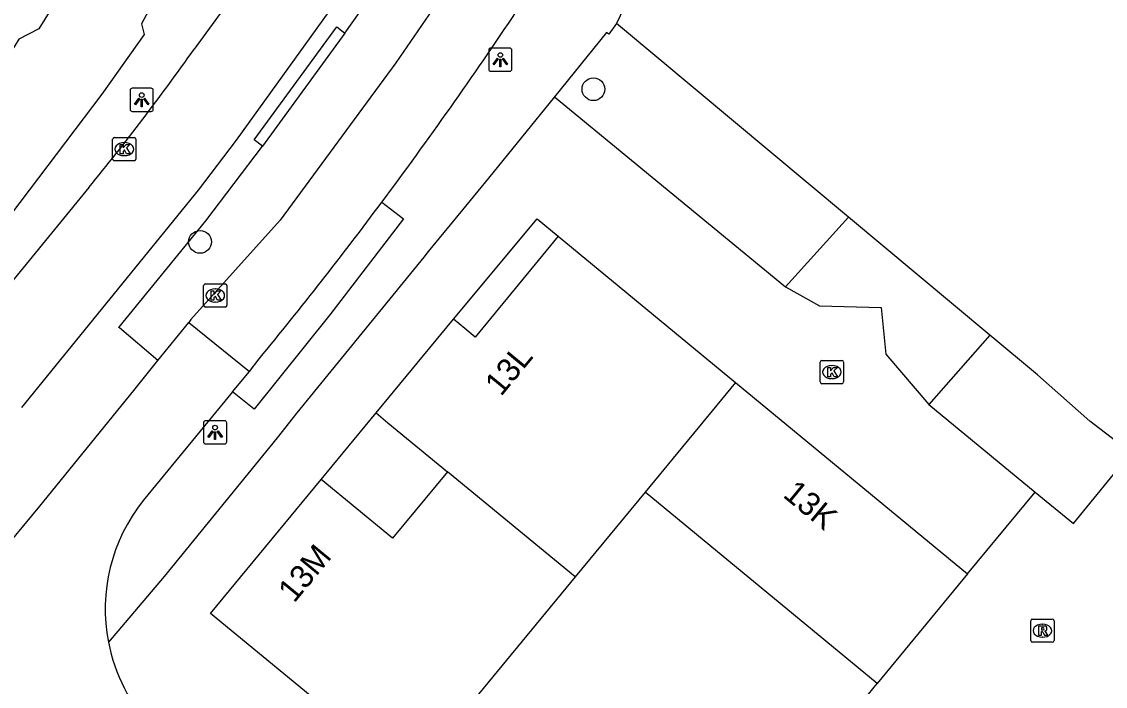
# Model space of a CAD drawing. Extents: x 161772 to 163123, y 383092 to 383917.
# Drawn here: x 161951.08 to 161997.61, y 383296.33 to 383324.88 of the extents above; entities that cross this region are included whole.
import ezdxf

# ---------------------------------------------------------------- set-up
doc = ezdxf.new("R2010")
doc.units = 0
for name, color, linetype in [('IMGEO_Berm_open', 7, 'Continuous'), ('IMGEO_Boom', 7, 'Continuous'), ('IMGEO_Fietspad_gesloten', 7, 'Continuous'), ('IMGEO_Groenvoorziening', 7, 'Continuous'), ('IMGEO_Kolk', 7, 'Continuous'), ('IMGEO_Lichtpunt', 7, 'Continuous'), ('IMGEO_Pand', 7, 'Continuous'), ('IMGEO_Pand_nummerreeks', 7, 'Continuous'), ('IMGEO_Parkeervlak_open', 7, 'Continuous'), ('IMGEO_Rijbaan_lokaal_gesloten', 7, 'Continuous'), ('IMGEO_Rijbaan_lokaal_open', 7, 'Continuous'), ('IMGEO_Rioolput', 7, 'Continuous'), ('IMGEO_Voetpad_open', 7, 'Continuous')]:
    doc.layers.add(name, color=color, linetype=linetype)

msp = doc.modelspace()

# ---------------------------------------------------------------- linework, layer by layer
at = {"layer": 'IMGEO_Berm_open'}
msp.add_lwpolyline([(161961.426, 383319.531), (161961.064, 383319.803), (161964.615, 383324.66), (161964.958, 383324.39)], dxfattribs=at)
at = {"layer": 'IMGEO_Boom'}
for centre in [(161975.629, 383321.983), (161958.739, 383315.426)]:
    msp.add_circle(centre, 0.489, dxfattribs=at)
at = {"layer": 'IMGEO_Fietspad_gesloten'}
for points in [[(161961.539, 383327.899), (161958.488, 383323.707)], [(161951.08, 383308.304), (161958.672, 383317.649), (161960.302, 383319.794), (161965.764, 383327.377)], [(161953.961, 383317.758), (161942.798, 383304.121), (161935.389, 383295.477), (161886.612, 383242.159)]]:
    msp.add_lwpolyline(points, dxfattribs=at)
msp.add_arc((161873.405, 383383.756), 104.139, 320.6731, 324.78693, dxfattribs=at)
at = {"layer": 'IMGEO_Groenvoorziening'}
for points in [[(161983.878, 383313.491), (161986.582, 383316.493)], [(161992.656, 383311.418), (161990.027, 383308.434)]]:
    msp.add_lwpolyline(points, dxfattribs=at)
at = {"layer": 'IMGEO_Kolk'}
for p, q in [((161955.062, 383319.909), (161955.914, 383319.909)), ((161954.987, 383318.983), (161954.987, 383319.835)), ((161955.475, 383319.689), (161955.5, 383319.689)), ((161955.988, 383319.835), (161955.988, 383318.983)), ((161955.498, 383319.129), (161955.473, 383319.129)), ((161955.914, 383318.909), (161955.062, 383318.909)), ((161958.894, 383312.695), (161958.894, 383313.547)), ((161958.969, 383313.621), (161959.821, 383313.621)), ((161959.382, 383313.401), (161959.407, 383313.401)), ((161959.895, 383313.547), (161959.895, 383312.695)), ((161959.821, 383312.621), (161958.969, 383312.621)), ((161959.405, 383312.841), (161959.38, 383312.841)), ((161985.367, 383309.406), (161985.367, 383310.258)), ((161985.442, 383310.332), (161986.294, 383310.332)), ((161985.855, 383310.112), (161985.88, 383310.112)), ((161986.368, 383310.258), (161986.368, 383309.406)), ((161986.294, 383309.332), (161985.442, 383309.332)), ((161985.878, 383309.552), (161985.853, 383309.552))]:
    msp.add_line(p, q, dxfattribs=at)
for points in [[(161955.062, 383319.909), (161955.914, 383319.909)], [(161954.987, 383318.983), (161954.987, 383319.835)], [(161955.308, 383319.609), (161955.431, 383319.609), (161955.431, 383319.458), (161955.561, 383319.609), (161955.725, 383319.609), (161955.579, 383319.458), (161955.732, 383319.209), (161955.58, 383319.209), (161955.495, 383319.373), (161955.431, 383319.306), (161955.431, 383319.209), (161955.308, 383319.209), (161955.308, 383319.609)], [(161955.988, 383319.835), (161955.988, 383318.983)], [(161955.914, 383318.909), (161955.062, 383318.909)], [(161958.894, 383312.695), (161958.894, 383313.547)], [(161958.969, 383313.621), (161959.821, 383313.621)], [(161959.895, 383313.547), (161959.895, 383312.695)], [(161959.215, 383313.321), (161959.338, 383313.321), (161959.338, 383313.17), (161959.468, 383313.321), (161959.632, 383313.321), (161959.486, 383313.17), (161959.639, 383312.921), (161959.487, 383312.921), (161959.402, 383313.085), (161959.338, 383313.018), (161959.338, 383312.921), (161959.215, 383312.921), (161959.215, 383313.321)], [(161959.821, 383312.621), (161958.969, 383312.621)], [(161985.367, 383309.406), (161985.367, 383310.258)], [(161985.442, 383310.332), (161986.294, 383310.332)], [(161986.368, 383310.258), (161986.368, 383309.406)], [(161985.688, 383310.032), (161985.811, 383310.032), (161985.811, 383309.881), (161985.941, 383310.032), (161986.105, 383310.032), (161985.959, 383309.881), (161986.112, 383309.632), (161985.96, 383309.632), (161985.875, 383309.796), (161985.811, 383309.729), (161985.811, 383309.632), (161985.688, 383309.632), (161985.688, 383310.032)], [(161986.294, 383309.332), (161985.442, 383309.332)]]:
    msp.add_lwpolyline(points, dxfattribs=at)
for centre, start, end in [((161955.064, 383319.833), 91.552, 178.448), ((161955.064, 383319.833), 91.552, 178.448), ((161955.912, 383319.833), 1.552, 88.448), ((161955.912, 383319.833), 1.552, 88.448), ((161955.064, 383318.985), 181.552, 268.448), ((161955.064, 383318.985), 181.552, 268.448), ((161955.912, 383318.985), 271.552, 358.448), ((161955.912, 383318.985), 271.552, 358.448), ((161958.971, 383313.545), 91.552, 178.448), ((161958.971, 383313.545), 91.552, 178.448), ((161959.819, 383313.545), 1.552, 88.448), ((161959.819, 383313.545), 1.552, 88.448), ((161958.971, 383312.697), 181.552, 268.448), ((161958.971, 383312.697), 181.552, 268.448), ((161959.819, 383312.697), 271.552, 358.448), ((161959.819, 383312.697), 271.552, 358.448), ((161985.444, 383310.256), 91.552, 178.448), ((161985.444, 383310.256), 91.552, 178.448), ((161986.292, 383310.256), 1.552, 88.448), ((161986.292, 383310.256), 1.552, 88.448), ((161985.444, 383309.408), 181.552, 268.448), ((161985.444, 383309.408), 181.552, 268.448), ((161986.292, 383309.408), 271.552, 358.448), ((161986.292, 383309.408), 271.552, 358.448)]:
    msp.add_arc(centre, 0.0765, start, end, dxfattribs=at)
for centre, major_axis, ratio, start_param, end_param in [((161955.474, 383319.409), (-0.387, 0.002), 0.722429, 4.712389, 7.853982), ((161955.499, 383319.409), (-0.39, 0.002), 0.717154, 1.570796, 4.712389), ((161959.381, 383313.121), (-0.387, 0.002), 0.722429, 4.712389, 7.853982), ((161959.406, 383313.121), (-0.39, 0.002), 0.717154, 1.570796, 4.712389), ((161985.854, 383309.832), (-0.387, 0.002), 0.722429, 4.712389, 7.853982), ((161985.879, 383309.832), (-0.39, 0.002), 0.717154, 1.570796, 4.712389)]:
    msp.add_ellipse(centre, major_axis=major_axis, ratio=ratio, start_param=start_param, end_param=end_param, dxfattribs=at)
at = {"layer": 'IMGEO_Lichtpunt'}
for p, q in [((161971.133, 383323.654), (161971.133, 383322.847)), ((161971.133, 383323.654), (161971.133, 383322.847)), ((161972.035, 383323.749), (161971.227, 383323.749)), ((161972.035, 383323.749), (161971.227, 383323.749)), ((161972.129, 383322.847), (161972.129, 383323.654)), ((161972.129, 383322.847), (161972.129, 383323.654)), ((161971.227, 383322.753), (161972.035, 383322.753)), ((161971.227, 383322.753), (161972.035, 383322.753)), ((161955.736, 383321.933), (161955.736, 383321.126)), ((161955.736, 383321.933), (161955.736, 383321.126)), ((161956.638, 383322.028), (161955.83, 383322.028)), ((161956.638, 383322.028), (161955.83, 383322.028)), ((161956.732, 383321.126), (161956.732, 383321.933)), ((161956.732, 383321.126), (161956.732, 383321.933)), ((161955.83, 383321.032), (161956.638, 383321.032)), ((161955.83, 383321.032), (161956.638, 383321.032)), ((161958.886, 383307.647), (161958.886, 383306.84)), ((161958.886, 383307.647), (161958.886, 383306.84)), ((161959.788, 383307.742), (161958.98, 383307.742)), ((161959.788, 383307.742), (161958.98, 383307.742)), ((161959.882, 383306.84), (161959.882, 383307.647)), ((161959.882, 383306.84), (161959.882, 383307.647)), ((161958.98, 383306.746), (161959.788, 383306.746)), ((161958.98, 383306.746), (161959.788, 383306.746))]:
    msp.add_line(p, q, dxfattribs=at)
for points in [[(161971.507, 383323.318), (161971.546, 383323.29), (161971.358, 383323.028), (161971.32, 383323.055), (161971.507, 383323.318)], [(161971.609, 383323.27), (161971.656, 383323.27), (161971.656, 383322.948), (161971.609, 383322.948), (161971.609, 383323.27)], [(161971.719, 383323.29), (161971.757, 383323.317), (161971.944, 383323.055), (161971.905, 383323.027), (161971.719, 383323.29)], [(161956.11, 383321.597), (161956.149, 383321.569), (161955.961, 383321.307), (161955.923, 383321.334), (161956.11, 383321.597)], [(161956.212, 383321.549), (161956.259, 383321.549), (161956.259, 383321.227), (161956.212, 383321.227), (161956.212, 383321.549)], [(161956.322, 383321.569), (161956.36, 383321.596), (161956.547, 383321.334), (161956.508, 383321.306), (161956.322, 383321.569)], [(161959.26, 383307.311), (161959.299, 383307.283), (161959.111, 383307.021), (161959.073, 383307.048), (161959.26, 383307.311)], [(161959.472, 383307.283), (161959.51, 383307.31), (161959.697, 383307.048), (161959.658, 383307.02), (161959.472, 383307.283)], [(161959.362, 383307.263), (161959.409, 383307.263), (161959.409, 383306.941), (161959.362, 383306.941), (161959.362, 383307.263)]]:
    msp.add_lwpolyline(points, dxfattribs=at)
for centre in [(161971.632, 383323.452), (161956.235, 383321.731), (161959.385, 383307.445)]:
    msp.add_circle(centre, 0.0994, dxfattribs=at)
for centre, start, end in [((161971.227, 383323.654), 90, 180), ((161971.227, 383323.654), 90, 180), ((161972.035, 383323.654), 0, 90), ((161972.035, 383323.654), 0, 90), ((161971.227, 383322.847), 180, 270), ((161971.227, 383322.847), 180, 270), ((161972.035, 383322.847), 270, 0), ((161972.035, 383322.847), 270, 360), ((161955.83, 383321.933), 90, 180), ((161955.83, 383321.933), 90, 180), ((161956.638, 383321.933), 0, 90), ((161956.638, 383321.933), 0, 90), ((161955.83, 383321.126), 180, 270), ((161955.83, 383321.126), 180, 270), ((161956.638, 383321.126), 270, 0), ((161956.638, 383321.126), 270, 360), ((161958.98, 383307.647), 90, 180), ((161958.98, 383307.647), 90, 180), ((161959.788, 383307.647), 0, 90), ((161959.788, 383307.647), 0, 90), ((161958.98, 383306.84), 180, 270), ((161958.98, 383306.84), 180, 270), ((161959.788, 383306.84), 270, 0), ((161959.788, 383306.84), 270, 360)]:
    msp.add_arc(centre, 0.0946, start, end, dxfattribs=at)
at = {"layer": 'IMGEO_Pand'}
for points in [[(161989.921, 383365.674), (161989.19, 383361.225), (161988.345, 383356.979), (161987.354, 383352.859), (161986.206, 383348.804), (161984.894, 383344.76), (161981.324, 383334.666), (161976.625, 383324.811)], [(161952.405, 383326.556), (161952.2, 383326.215), (161952.329, 383325.412), (161951.823, 383324.571), (161950.957, 383324.126), (161950.17, 383322.838), (161949.7, 383323.121), (161947.088, 383318.774), (161944.388, 383320.397), (161944.122, 383319.954), (161941.457, 383321.557), (161941.061, 383320.898), (161937, 383323.342), (161935.499, 383324.245), (161938.424, 383329.111), (161937.559, 383329.631), (161940.15, 383333.943), (161941.394, 383333.174), (161948.12, 383329.132), (161952.405, 383326.556)], [(161986.582, 383316.493), (161976.625, 383324.811)], [(161992.656, 383311.418), (161986.582, 383316.493)], [(161974.112, 383315.664), (161970.549, 383311.337), (161970.102, 383311.705), (161969.617, 383312.103)], [(161974.112, 383315.664), (161981.734, 383309.38)], [(161966.298, 383308.075), (161969.617, 383312.103)], [(161998.722, 383306.358), (161996.945, 383307.727), (161994.696, 383309.714), (161992.656, 383311.418)], [(161981.734, 383309.38), (161977.847, 383304.666)], [(161981.734, 383309.38), (161991.697, 383301.165)], [(161966.298, 383308.075), (161966.808, 383307.655), (161969.361, 383305.552)], [(161969.361, 383305.552), (161967.005, 383302.695), (161963.945, 383305.221)], [(161974.85, 383301.031), (161969.361, 383305.552)], [(161967.744, 383292.413), (161959.192, 383299.463), (161963.945, 383305.221)], [(161977.847, 383304.666), (161974.85, 383301.031)], [(161987.81, 383296.45), (161977.847, 383304.666)], [(161974.85, 383301.031), (161967.744, 383292.413)], [(161991.697, 383301.165), (161987.81, 383296.45)], [(161987.446, 383295.992), (161987.81, 383296.45)]]:
    msp.add_lwpolyline(points, dxfattribs=at)
at = {"layer": 'IMGEO_Parkeervlak_open'}
for points in [[(161964.958, 383324.39), (161966.144, 383326.081)], [(161964.958, 383324.39), (161961.426, 383319.531)], [(161956.93, 383310.332), (161955.277, 383311.727), (161955.257, 383311.744), (161958.985, 383316.324), (161961.426, 383319.531)]]:
    msp.add_lwpolyline(points, dxfattribs=at)
at = {"layer": 'IMGEO_Rijbaan_lokaal_gesloten'}
for points in [[(161956.93, 383310.332), (161958.255, 383311.968)], [(161958.255, 383311.968), (161960.862, 383309.86)], [(161938.545, 383288.593), (161942.733, 383293.261), (161946.965, 383298.168), (161951.858, 383304.076), (161955.895, 383309.039), (161956.93, 383310.332)], [(161960.136, 383308.977), (161960.862, 383309.86)], [(161960.136, 383308.977), (161956.302, 383304.313)]]:
    msp.add_lwpolyline(points, dxfattribs=at)
for centre, radius, start, end in [((161962.117, 383299.653), 7.452, 141.2903, 191.045), ((161962.124, 383299.656), 7.459, 191.0593, 223.3554)]:
    msp.add_arc(centre, radius, start, end, dxfattribs=at)
at = {"layer": 'IMGEO_Rijbaan_lokaal_open'}
for points in [[(161968.871, 383325.63), (161967.141, 383323.116), (161962.174, 383316.363), (161958.349, 383312.084), (161958.255, 383311.968)], [(161960.862, 383309.86), (161961.284, 383310.407)], [(161994.594, 383304.679), (161996.242, 383303.323), (161998.722, 383306.358)], [(161991.697, 383301.165), (161994.594, 383304.679)]]:
    msp.add_lwpolyline(points, dxfattribs=at)
for centre, radius, start, end in [((161810.841, 383433.102), 194.147, 323.31816, 326.28176), ((161828.645, 383419.611), 171.809, 320.53481, 323.37939)]:
    msp.add_arc(centre, radius, start, end, dxfattribs=at)
at = {"layer": 'IMGEO_Rioolput'}
for p, q in [((161994.407, 383298.297), (161994.407, 383299.149)), ((161994.482, 383299.223), (161995.334, 383299.223)), ((161994.895, 383299.003), (161994.92, 383299.003)), ((161995.408, 383299.149), (161995.408, 383298.297)), ((161995.334, 383298.223), (161994.482, 383298.223)), ((161994.918, 383298.443), (161994.893, 383298.443))]:
    msp.add_line(p, q, dxfattribs=at)
for points in [[(161994.407, 383298.297), (161994.407, 383299.149)], [(161994.482, 383299.223), (161995.334, 383299.223)], [(161994.996, 383298.921), (161994.744, 383298.923), (161994.744, 383298.523)], [(161995.408, 383299.149), (161995.408, 383298.297)], [(161994.744, 383298.523), (161994.868, 383298.523), (161994.868, 383298.685), (161994.879, 383298.685)], [(161994.922, 383298.842), (161994.868, 383298.842), (161994.868, 383298.761)], [(161994.868, 383298.761), (161994.92, 383298.761)], [(161994.926, 383298.656), (161994.997, 383298.523), (161995.137, 383298.523), (161995.072, 383298.649)], [(161995.334, 383298.223), (161994.482, 383298.223)]]:
    msp.add_lwpolyline(points, dxfattribs=at)
for centre, radius, start, end in [((161994.484, 383299.147), 0.0765, 91.552, 178.448), ((161994.484, 383299.147), 0.0765, 91.552, 178.448), ((161994.995, 383298.811), 0.109, 350.3612, 89.416), ((161995.332, 383299.147), 0.0765, 1.552, 88.448), ((161995.332, 383299.147), 0.0765, 1.552, 88.448), ((161994.878, 383298.632), 0.0533, 26.0293, 88.6989), ((161994.904, 383298.95), 0.19, 274.7715, 282.9687), ((161994.928, 383298.746), 0.0964, 77.0061, 93.1865), ((161994.942, 383298.803), 0.0378, 276.6634, 79.6772), ((161994.993, 383298.811), 0.112, 277.5842, 350.9817), ((161994.977, 383298.596), 0.108, 29.5134, 73.7905), ((161994.484, 383298.299), 0.0765, 181.552, 268.448), ((161994.484, 383298.299), 0.0765, 181.552, 268.448), ((161995.332, 383298.299), 0.0765, 271.552, 358.448), ((161995.332, 383298.299), 0.0765, 271.552, 358.448)]:
    msp.add_arc(centre, radius, start, end, dxfattribs=at)
for centre, major_axis, ratio, start_param, end_param in [((161994.894, 383298.723), (-0.387, 0.002), 0.722429, 4.712389, 7.853982), ((161994.919, 383298.723), (-0.39, 0.002), 0.717154, 1.570796, 4.712389)]:
    msp.add_ellipse(centre, major_axis=major_axis, ratio=ratio, start_param=start_param, end_param=end_param, dxfattribs=at)
at = {"layer": 'IMGEO_Voetpad_open'}
for points in [[(161959.195, 383331.001), (161957.936, 383328.362), (161958.095, 383328.287), (161956.227, 383324.789), (161956.346, 383324.34), (161954.519, 383321.774), (161948.264, 383313.526), (161946.008, 383310.656), (161937.818, 383301.48), (161938.061, 383301.283), (161925, 383287.557), (161922.701, 383285.219), (161916.662, 383279.077), (161912.104, 383283.459)], [(161976.625, 383324.811), (161976.296, 383324.342), (161976.198, 383324.422), (161973.952, 383321.654)], [(161973.952, 383321.654), (161971.121, 383318.165), (161969.684, 383316.394), (161968.541, 383315.009), (161968.344, 383314.77), (161962.893, 383308.075), (161962.743, 383307.887), (161962.048, 383307.014), (161957.202, 383301.049), (161954.803, 383298.225)], [(161973.952, 383321.654), (161983.878, 383313.491)], [(161966.54, 383317.124), (161967.474, 383316.416), (161964.315, 383312.287), (161961.056, 383308.236), (161960.136, 383308.977)], [(161969.617, 383312.103), (161973.219, 383316.411), (161974.112, 383315.664)], [(161983.878, 383313.491), (161985.343, 383312.682), (161987.983, 383312.612), (161988.192, 383310.595), (161990.027, 383308.434)], [(161990.027, 383308.434), (161994.594, 383304.679)], [(161963.945, 383305.221), (161966.298, 383308.075)]]:
    msp.add_lwpolyline(points, dxfattribs=at)

# ---------------------------------------------------------------- texts
at = {"layer": 'IMGEO_Pand_nummerreeks'}
for s, rotation, p in [('13L', 50.5291, (161971.662, 383308.756)), ('13K', 320.4946, (161983.722, 383304.499)), ('13M', 50.4604, (161962.78, 383299.882))]:
    msp.add_text(s, height=1, rotation=rotation, dxfattribs=at).set_placement(p)

doc.saveas('drawing.dxf')
